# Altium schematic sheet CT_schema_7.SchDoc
size 280 x 153 mm
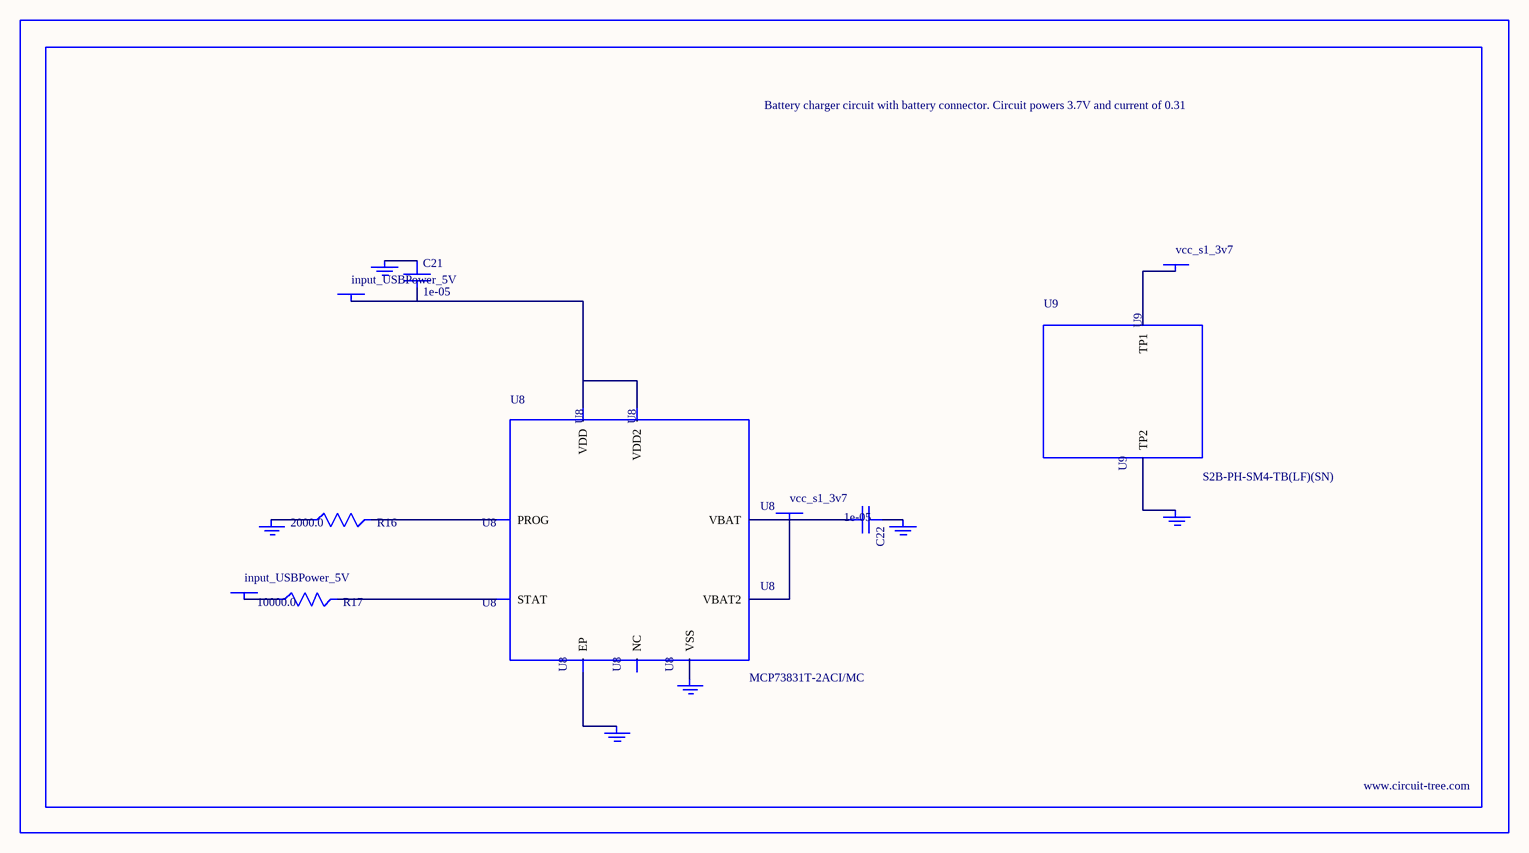
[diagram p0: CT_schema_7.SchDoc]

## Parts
BORDER6  (no value)
C21  1e-05  [C1206]
C22  1e-05  [C1206]
GND_INSTANCE_6_0  (no value)
GND_INSTANCE_6_1  (no value)
GND_INSTANCE_6_2  (no value)
GND_INSTANCE_6_3  (no value)
GND_INSTANCE_6_4  (no value)
GND_INSTANCE_6_5  (no value)
POWER_INSTANCE_6_0  input_USBPower_5V
POWER_INSTANCE_6_1  input_USBPower_5V
POWER_INSTANCE_6_2  vcc_s1_3v7
POWER_INSTANCE_6_3  vcc_s1_3v7
R16  2000.0  [R0603]
R17  10000.0  [R0603]
U8  MCP73831T-2ACI/MC  [DFN8_2X3MC]
U9  S2B-PH-SM4-TB(LF)(SN)  [JST-2-SMD]

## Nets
NetC21_1: C21.1 GND_INSTANCE_6_0.0(GND)
NetC21_2: C21.2 POWER_INSTANCE_6_0.0(PWR) U8.1(VDD) U8.2(VDD2)
NetC22_1: C22.1 GND_INSTANCE_6_1.0(GND)
NetC22_2: C22.2 POWER_INSTANCE_6_2.0(PWR) U8.3(VBAT) U8.4(VBAT2)
NetGND_INSTANCE_6_2_0: GND_INSTANCE_6_2.0(GND) R16.1
NetGND_INSTANCE_6_3_0: GND_INSTANCE_6_3.0(GND) U8.9(EP)
NetGND_INSTANCE_6_4_0: GND_INSTANCE_6_4.0(GND) U8.6(VSS)
NetGND_INSTANCE_6_5_0: GND_INSTANCE_6_5.0(GND) U9.2(TP2)
NetPOWER_INSTANCE_6_1_0: POWER_INSTANCE_6_1.0(PWR) R17.1
NetPOWER_INSTANCE_6_3_0: POWER_INSTANCE_6_3.0(PWR) U9.1(TP1)
NetR16_2: R16.2 U8.8(PROG)
NetR17_2: R17.2 U8.5(STAT)

Not connected (* = marked no-connect by the designer): U8 7(NC)

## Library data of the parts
BORDER6 = BORDER_PAGE6
C21 C22 = C1206C106K3RACTU
GND_INSTANCE_6_0-GND_INSTANCE_6_5 = GND
POWER_INSTANCE_6_0-POWER_INSTANCE_6_3 = PWR
R16 = RC0603JR-072KL
R17 = RC0603JR-0710KL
